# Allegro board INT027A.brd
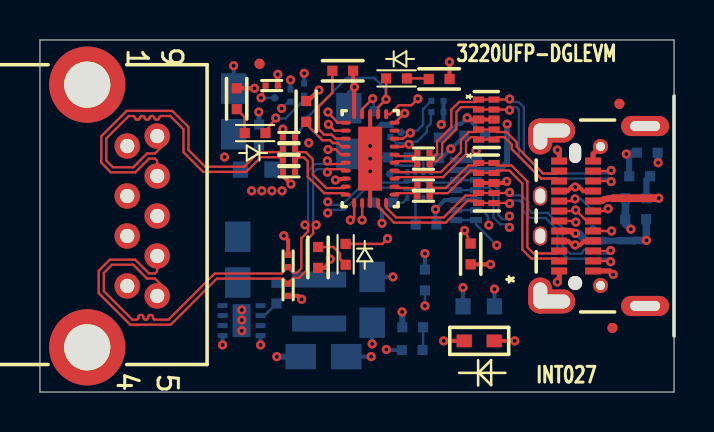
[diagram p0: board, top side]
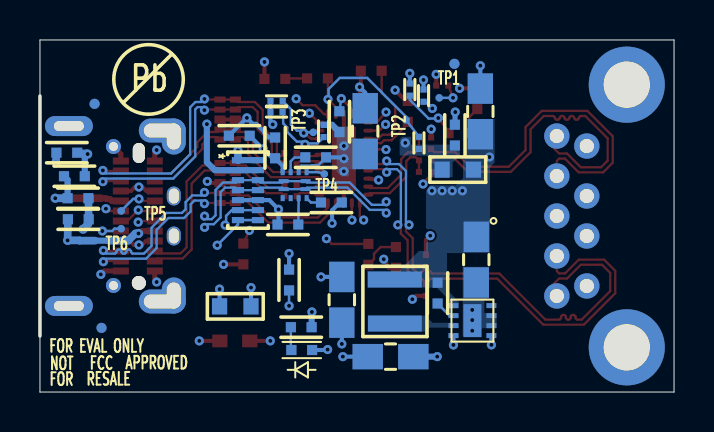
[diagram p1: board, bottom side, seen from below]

Outline 31.74 x 17.61 mm; copper layers: TOP, L2_GND, L3_PWR, L4_PWR, L5_GND, BOTTOM. Coordinates in mm from the lower left corner of the outline.
Outline path: 0,17.61 0,0 31.74,0 31.74,17.61 0,17.61

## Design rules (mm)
net group DIFFPAIR0: nets USB2_N0 USB2_P0
net group DIFFPAIR1: nets CTX1N CTX1P
net group DIFFPAIR2: nets CRX2N CRX2P
net group DIFFPAIR3: nets CTX2N CTX2P
net group DIFFPAIR4: nets CRX1N CRX1P
net group DIFFPAIR5: nets USB3_RX0N USB3_RX0P
net group DIFFPAIR6: nets USB3_TX0N USB3_TX0P
net group DIFFPAIR7: nets CTX2N_C CTX2P_C
net group DIFFPAIR8: nets CTX1N_C CTX1P_C
net group DP1: nets USB3_RX0N_C USB3_RX0P_C

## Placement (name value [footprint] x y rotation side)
C1  0.5uF  [0201]  12.47 12.16 0 top
C2  0.5uF  [0201]  19.2 11.96 0 top
C3  0.5uF  [0201]  12.46 11.59 0 top
C4  0.5uF  [0201]  19.2 11.4 0 top
C5  0.5uF  [0201]  19.2 10.36 0 top
C6  0.5uF  [0201]  19.2 9.8 0 top
C7  22uF  [0805]  9.7 14.04 90 bottom
C8  47uF  [0805]  15.46 13.05 270 bottom
C9  0.1uF  [0402]  10.97 12.85 90 bottom
C10  0.1uF  [0402]  21.77 12.82 0 bottom
C11  0.01uF  [0402]  19.97 12.21 90 bottom
C12  0.1uF  [0402]  17.94 11.74 180 bottom
C13  0.1uF  [0402]  19.33 8.38 0 bottom
C14  10uF  [0805]  9.9 6.62 270 bottom
C15  10uF  [0805]  16.63 4.62 90 bottom
C16  NC, 10uF  [0603]  21.97 4.28 0 bottom
C17  10uF  [0805]  14.19 1.77 0 bottom
D1  LED RED 0402  [LED_0402]  17.85 15.69 0 top
D2  LED YLW 0402  [LED_0402]  10.77 12.96 180 top
D3  LED Orange 0402  [LED_0402]  15.3 6.89 270 top
D4  ESD5Z6.0T1G  [SOD_523]  21.99 2.56 180 top
D5  LED Green  [LED_0402]  18.64 2.1 180 bottom
FB1  220 @ 100MHZ  [0603]  10.83 11.13 0 bottom
J1  USB3_TypeA_Connector  [USB3_TYPEA]  5.87 8.81 270 top
J2  TypeC_Receptacle_DualSMT_TOP  [USB_TYPEC_UT1211]  26.79 8.81 90 top
L1  1uH  [IND_NR3015]  13.98 4.53 90 bottom
NOREF  -  []  0 0 0 top
NOREF#2  -  []  -8.44 36.96 0 top
NOREF#3  -  []  46.18 36.96 0 top
NOREF#4  -  []  31.74 0 0 top
NOREF#5  -  []  -8.73 -17.08 0 top
NOREF#6  -  []  0 0 0 top
NOREF#7  -  [unnamed#2]  10.99 16.42 0 top
NOREF#8  -  [unnamed#2]  28.66 3.21 0 top
NOREF#9  -  [unnamed#2]  29.01 14.42 0 top
NOREF#10  -  []  0 17.61 0 top
NOREF#11  -  []  -67.49 -63.26 0 top
NOREF#12  -  []  69.68 -27.35 0 top
NOREF#13  -  [unnamed#2]  29.01 14.42 180 bottom
NOREF#14  -  [unnamed#2]  28.66 3.21 180 bottom
NOREF#15  -  [unnamed#2]  11 16.42 180 bottom
R1  NC, 10K  [0402]  15.16 16.07 0 top
R2  500R  [0402]  19.98 15.66 180 top
R3  200K  [0201]  11.6 15.33 180 top
R4  500R  [0402]  9.85 14.67 270 top
R5  4.7K  [0402]  13.33 14.04 90 top
R6  100K  [0201]  12.46 12.73 180 top
R7  100K  [0201]  12.47 11.02 180 top
R8  900K  [0402]  21.56 6.91 270 top
R9  500R  [0402]  13.92 6.73 90 top
R10  100K  [0201]  12.42 6.56 90 top
R11  100K  [0201]  12.42 5.12 270 top
R12  200K  [0201]  13.23 15.13 270 bottom
R13  200K  [0201]  12.54 14.83 270 bottom
R14  200K  [0201]  19.9 14.56 180 bottom
R15  NC, 10K  [0201]  19.9 14.01 180 bottom
R16  0  [0402]  16.75 13.53 90 bottom
R17  NC, 10K  [0201]  17.55 13.06 90 bottom
R18  200K  [0201]  12.77 12.46 90 bottom
R19  0  [0402]  30.4 11.97 180 bottom
R20  NC, 0  [0402]  30.02 10.79 180 bottom
R21  0  [0402]  29.84 9.7 180 bottom
R22  1.6K  [0402]  17.16 9.48 180 bottom
R23  NC, 0  [0402]  29.82 8.64 180 bottom
R24  0  [0402]  19.27 5.61 270 bottom
R25  178K  [0402]  11.84 4.95 90 bottom
R26  330  [0402]  18.66 3.24 180 bottom
TP1  15-mil TEST PAD  [15_MIL_ROUND_PROBE_POINT]  11.76 14.72 180 bottom
TP2  15-mil TEST PAD  [15_MIL_ROUND_PROBE_POINT]  13.42 13.61 90 bottom
TP3  15-mil TEST PAD  [15_MIL_ROUND_PROBE_POINT]  18.07 12.99 90 bottom
TP4  15-mil TEST PAD  [15_MIL_ROUND_PROBE_POINT]  17.51 10.91 0 bottom
TP5  15-mil TEST PAD  [15_MIL_ROUND_PROBE_POINT]  27.68 9.06 90 bottom
TP6  15-mil TEST PAD  [15_MIL_ROUND_PROBE_POINT]  27.68 8.17 90 bottom
U1  HD3SS3220  [RNH_QFN-30]  16.53 11.68 0 top
U2  TPD4E05U06  [DQA]  22.35 13.63 270 top
U3  TPD4E05U06  [DQA]  22.35 10.46 270 top
U4  TUSB211RWB  [RWB]  18.99 10.35 180 bottom
U5  TPD6E05U06  [RVZ]  21.33 10.1 270 bottom
U6  TPS62082DSGT  [DSG]  10.09 3.57 0 bottom

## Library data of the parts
C1-C9 C15 = CAP NP
C10-C13 = cc0402
C14 C16 C17 = CAP
D1-D3 D5 = DIODE_0
D4 = DIODE TAZ
FB1 = FERRITE BEAD
J1 = USB3_TYPEA_CONNECTOR
J2 = USBTypeC_Receptacle_TOPMount_0
L1 = INDUCTOR
R1 R5 R8 = RESISTOR
R2 R4 R9 R16 R19-R21 R23 R24 R26 = R
R3 R6 R7 R10-R15 R17 R18 = R_2
R22 = r0402
R25 = RES
TP1-TP6 = TEST POINT
U1 = HD3SS3220_0
U2 U3 = TPD4E05U06
U4 = TUSB211RWB
U5 = TPD6E05U06
U6 = TPS62082_0

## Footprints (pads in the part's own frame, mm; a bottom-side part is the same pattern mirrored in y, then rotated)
15_MIL_ROUND_PROBE_POINT
  round 0.381 smd: 1(0,0)
0201
  rect 0.305x0.305 smd: 1(-0.305,0) 2(0.305,0)
0402
  rect 0.508x0.508 smd: 1(-0.521,0) 2(0.521,0)
0603
  rect 0.762x0.813 smd: 1(-0.787,0) 2(0.787,0)
0805
  rect 1.524x1.27 smd: 1(-1.143,0) 2(1.143,0)
DQA
  rect 0.305x0.559 smd: 1(-1,-0.385) 2(-0.5,-0.385) 4(0.5,-0.385) 5(1,-0.385) 6(1,0.385) 7(0.5,0.385) 9(-0.5,0.385) 10(-1,0.385)
  rect 0.406x0.559 smd: 3(0,-0.385) 8(0,0.385)
DSG
  rect 0.5x0.25 smd: 1(-0.95,0.75) 2(-0.95,0.25) 3(-0.95,-0.25) 4(-0.95,-0.75) 5(0.95,-0.75) 6(0.95,-0.25) 7(0.95,0.25) 8(0.95,0.75)
  rect 0.9x1.65 smd: 9(0,0)
IND_NR3015
  rect 0.8x2.7 smd: 1(-1.1,0) 2(1.1,0)
LED_0402
  rect 0.508x0.508 smd: 1(-0.521,0) 2(0.521,0)
RNH_QFN-30
  oval 0.5x0.2 smd: 1(-1.225,1.8) 2(-1.225,1.4) 3(-1.225,1) 4(-1.225,0.6) 5(-1.225,0.2) 6(-1.225,-0.2) 7(-1.225,-0.6) 8(-1.225,-1) 9(-1.225,-1.4) 10(-1.225,-1.8) 16(1.225,-1.8) 17(1.225,-1.4) 18(1.225,-1) 19(1.225,-0.6) 20(1.225,-0.2) 21(1.225,0.2) 22(1.225,0.6) 23(1.225,1) 24(1.225,1.4) 25(1.225,1.8)
  oval 0.2x0.5 smd: 11(-0.8,-2.225) 12(-0.4,-2.225) 13(0,-2.225) 14(0.4,-2.225) 15(0.8,-2.225) 26(0.8,2.225) 27(0.4,2.225) 28(0,2.225) 29(-0.4,2.225) 30(-0.8,2.225)
  rect 1.2x3.2 smd: 31(0,0)
RVZ
  rect 0.305x0.61 smd: 1(-1.5,-0.5) 2(-1,-0.5) 3(-0.5,-0.5) 4(0,-0.5) 5(0.5,-0.5) 6(1,-0.5) 7(1.5,-0.5) 8(1.5,0.5) 9(1,0.5) 10(0.5,0.5) 11(0,0.5) 12(-0.5,0.5) 13(-1,0.5) 14(-1.5,0.5)
RWB
  rect 0.5x0.2 smd: 1(-0.55,0.2) 2(-0.55,-0.2) 7(0.55,-0.2) 8(0.55,0.2)
  rect 0.2x0.3 smd: 3(-0.6,-0.65) 4(-0.2,-0.65) 5(0.2,-0.65) 6(0.6,-0.65) 9(0.6,0.65) 10(0.2,0.65) 11(-0.2,0.65) 12(-0.6,0.65)
SOD_523
  rect 0.762x0.635 smd: 1(0.75,0) 2(-0.75,0)
unnamed#2
  round 0.508 smd: 1(0,0)
USB3_TYPEA
  round 1.27 hole 0.711: 1(-3.5,-1.5) 2(-1,-1.5) 3(1,-1.5) 4(3.5,-1.5) 5(4,0) 6(2,0) 7(0,0) 8(-2,0) 9(-4,0)
  round 3.81 hole 2.311: 10(-6.57,-3.5) 11(6.57,-3.5)
USB_TYPEC_UT1211
  round 0.7 hole 0.7 unplated: (-3.35,0)
  oval 1x0.6 hole 1x0.6 unplated: (3.15,0)
  round 0.75 hole 0.45: 1(-3.475,-1.27) 2(3.475,-1.27)
  oval 1x2.4 hole 0.5x1.5: 3(-4.5,-3.5) 4(4.5,-3.5)
  oval 0.95x0.7 hole 0.75x0.5: 5(-1,1.75) 6(1,1.75)
  oval 1.2x2.35 hole 0.7x1.85: 7(4.275,1.175) 8(-4.275,1.175)
  oval 1.8x1.2 hole 1.3x0.7: 9(-3.975,1.75) 10(3.975,1.75)
  rect 0.35x0.8 smd: A1(-2.75,0.8) A2(-2.25,0.8) A3(-1.75,0.8) A4(-1.25,0.8) A5(-0.75,0.8) A6(-0.25,0.8) A7(0.25,0.8) A8(0.75,0.8) A9(1.25,0.8) A10(1.75,0.8) A11(2.25,0.8) A12(2.75,0.8) B1(2.75,-0.9) B2(2.25,-0.9) B3(1.75,-0.9) B4(1.25,-0.9) B5(0.75,-0.9) B6(0.25,-0.9) B7(-0.25,-0.9) B8(-0.75,-0.9) B9(-1.25,-0.9) B10(-1.75,-0.9) B11(-2.25,-0.9) B12(-2.75,-0.9)

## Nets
5V_COM: C8.1 C15.1 C16.2(B) C17.2(B) D4.1(CATHODE) D5.2(A) J1.1(VBUS) J2.A4(VBUS1) J2.A9(VBUS2) J2.B4(VBUS3) J2.B9(VBUS4) R1.2 R2.1 R3.1 R4.1 R8.2 R9.1 R12.1 R13.1 R14.1 R15.1 U1.30(VDD5) U6.1(EN) U6.8(VIN)
GND: C7.2 C8.2 C9.2 C10.2 C11.2 C12.2 C13.2 C14.2(B) C15.2 C16.1(A) C17.1(A) D4.2(ANODE) J1.4(GND#4) J1.7(GND#7) J1.10(SHIELD0) J1.11(SHIELD1) J2.1(SHIELD1) J2.2(SHIELD2) J2.3(SHIELD3) J2.4(SHIELD4) J2.5(SHIELD5) J2.6(SHIELD6) J2.7(SHIELD7) J2.8(SHIELD8) J2.9(SHIELD9) J2.10(SHIELD10) J2.A1(GND0) J2.A12(GND1) J2.B1(GND2) J2.B12(GND3) R5.2 R6.2 R7.2 R10.2 R11.2 R16.1 R17.2 R22.2 R24.1 R26.2 U1.13(GND#13) U1.28(GND#28) U1.31(PPAD) U2.3(GND#3) U2.8(GND#8) U3.3(GND#3) U3.8(GND#8) U4.10(GND) U5.5(GND) U5.10(GND#10) U6.2(GND) U6.3(MODE) U6.9(PWPD)
VBUS_DET: R8.1 U1.5(VBUS_DET)
3P3V: C7.1 C10.1 C11.1 C14.1(A) FB1.1 L1.2 R25.2(B) U4.12(VCC) U6.5(VOS)
3P3V_VCC: C9.1 FB1.2 R18.1 U1.8(VCC33)
3220_ID: D1.1(K) R18.2 TP2.1 U1.27(ID)
ADDR: R15.2 R17.1 U1.22(ADDR)
C_CC1: J2.A5(CC1) R19.1 R23.1
C_CC2: J2.B5(CC2) R20.1 R21.1
CC1: R19.2 R20.2 U1.2(CC1) U5.1(NC1) U5.14(D1+)
CC2: R21.2 R23.2 U1.1(CC2) U5.2(NC2) U5.13(D1-)
CRX1N: J2.B10(SSRXN1) U1.15(RX1P) U3.4(D2+) U3.7(NC7)
CRX1P: J2.B11(SSRXP1) U1.14(RX1N) U3.5(D2-) U3.6(NC6)
CRX2N: J2.A10(SSRXN2) U1.18(RX2N) U2.5(D2-) U2.6(NC6)
CRX2P: J2.A11(SSRXP2) U1.19(RX2P) U2.4(D2+) U2.7(NC7)
CSBU1: J2.A8(SBU1) TP5.1 U5.7(NC6) U5.8(D3-)
CSBU2: J2.B8(SBU2) TP6.1 U5.6(NC5) U5.9(D3+)
CTX1N: C5.2 J2.A3(SSTXN1) U3.1(D1+) U3.10(NC10)
CTX1N_C: C5.1 U1.17(TX1P)
CTX1P: C6.2 J2.A2(SSTXP1) U3.2(D1-) U3.9(NC9)
CTX1P_C: C6.1 U1.16(TX1N)
CTX2N: C4.2 J2.B3(SSTXN2) U2.2(D1-) U2.9(NC9)
CTX2N_C: C4.1 U1.20(TX2N)
CTX2P: C2.2 J2.B2(SSTXP2) U2.1(D1+) U2.10(NC10)
CTX2P_C: C2.1 U1.21(TX2P)
CUR_MD: R1.1 U1.3(CURRENT_MODE)
DIR: R3.2 TP1.1 U1.11(DIR)
EN#_CC: R16.2 U1.29(ENN_CC)
EN#_MUX: R24.2 U1.12(ENN_MUX)
INT#_OUT3: R14.2 TP3.1 U1.23(INT_N_OUT3)
PORT: R5.1 U1.4(PORT)
SCL_OUT2: D2.1(K) R12.2 U1.26(SCL_OUT2)
SDA_OUT1: D3.1(K) R13.2 U1.25(SDA_OUT1)
U8_PG: R25.1(A) U6.6(PG)
U8_SW: L1.1 U6.7(SW)
USB2_N0: J1.2(DM) J2.A7(DN1) J2.B7(DN2) U4.1(D1M) U4.8(D2M) U5.3(NC3) U5.12(D2+)
USB2_P0: J1.3(DP) J2.A6(DP1) J2.B6(DP2) U4.2(D1P) U4.7(D2P) U5.4(NC4) U5.11(D2-)
USB3_RX0N: C1.1 J1.8(SSTXN)
USB3_RX0N_C: C1.2 R6.1 U1.9(RXP)
USB3_RX0P: C3.1 J1.9(SSTXP)
USB3_RX0P_C: C3.2 R7.1 U1.10(RXN)
USB3_TX0N: J1.5(SSRXN) R10.1 U1.6(TXP)
USB3_TX0P: J1.6(SSRXP) R11.1 U1.7(TXN)
VCONN_FAULT#: U1.24(VCONN_FAULT_N)
N16911818: C12.1 U4.11(VREG)
N16911898: C13.1 U4.5(RSTN)
N16911900: R22.1 U4.6(EQ)
N16922242: TP4.1 U4.9(ENA_HS)
N16960198: D5.1(K) R26.1
N16963575: D3.2(A) R9.2
N16963631: D2.2(A) R4.2
N16967109: D1.2(A) R2.2

Pads without a net: NOREF#7 1; NOREF#8 1; NOREF#9 1; NOREF#13 1; NOREF#14 1; NOREF#15 1; U4 3 4; U6 4

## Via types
v1: diameter 0.457, hole 0.203, TOP to BOTTOM, 100 vias

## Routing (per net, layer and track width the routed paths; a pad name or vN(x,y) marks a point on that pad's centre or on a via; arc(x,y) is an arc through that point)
5V_COM: length 22.7
  TOP w0.203: D4.1 v1(20.21,2.56) ; R1.2 15.68,15.32 v1(15.74,15.26) 15.73,15.25 U1.30 ; R9.1 14.28,6.21 v1(14.53,6.64) ; J2.B4 27.19,10.06 27,10.25 v1(26.79,10.25) 26.61,10.25 26.42,10.06 J2.A9 ; J2.A4 26.44,7.56 26.64,7.36 v1(26.79,7.36) 27.05,7.36 27.24,7.56 J2.B9 ; R8.2 v1(22.56,6.39) ; R3.1 v1(11.91,15.89) ; R4.1 v1(10.74,15.19) ; R2.1 v1(20.51,16.52)
  L4_PWR w0.203: 3.55,12.31 J1.1 ; J1.1 5.18,12.31 ; J1.1 4.37,13.12 ; J1.1 4.37,11.49
  BOTTOM w0.203: C15.1 v1(16.63,2.41) ; U6.8 v1(11.04,2.35) ; R12.1 v1(13.23,15.94) ; C8.1 15.46,14.98 v1(15.74,15.26) ; C17.2 v1(16.58,1.77) ; v1(20.09,13.39) 20.21,13.5 R15.1 20.2,14.01 R14.1 ; 18.14,2.1 D5.2 17.37,2.1 v1(17.34,2.13) ; C16.2 v1(22.75,5.15) ; U6.1 v1(9.14,2.36) ; R13.1 v1(12.54,15.61)
GND: length 117.5
  TOP w0.203: R11.2 12.93,4.81 v1(13.1,4.64) ; v1(23.37,10.54) 23.17,10.46 U3.8 U3.3 ; U1.28 v1(16.53,12.31) v1(16.53,11.68) v1(16.53,11.04) U1.13 ; R5.2 13.42,14.56 v1(13.96,15.11) ; D4.2 v1(23.77,2.56) ; U2.8 U2.3 21.47,13.63 v1(21.39,13.72) ; R6.2 v1(12.16,13.15) ; v1(12.21,7.82) 12.42,7.6 R10.2 ; R7.2 12.16,10.81 v1(12.57,10.41)
  TOP w0.254: v1(25.9,5.5) 25.99,5.6 J2.A1 ; J2.B12 28.53,6.06 v1(28.7,5.89) ; J2.A12 25.99,12.02 v1(25.9,12.11) ; J2.2 27.69,11.91 J2.B1
  L2_GND w0.203: 4.45,15.38 J1.10 2.37,13.29 ; J2.2 28.62,12.28 ; J2.2 28.06,12.83 ; J2.2 27.51,12.28 ; J2.2 28.06,11.73 ; J2.7 25.62,13.86 ; J2.7 24.27,13.08 ; J2.7 26.97,13.08 ; J2.5 25.57,7.81 ; J2.5 25.04,7.15 ; J2.5 24.52,7.81 ; J2.5 25.04,8.46 ; J1.4 4.37,6.12 ; J1.4 3.55,5.31 ; J1.4 5.18,5.31 ; J1.4 4.37,4.49 ; J2.3 30.3,4.98 ; J2.3 30.3,3.63 ; J2.3 28.92,4.31 ; 28.06,4.78 J2.1 ; J2.1 28.06,5.88 ; J2.1 27.51,5.33 ; J2.1 28.62,5.33 ; 24.27,4.83 J2.9 ; J2.9 25.04,5.91 ; J2.9 25.04,3.75 ; J2.6 25.04,10.46 ; J2.6 24.52,9.81 ; J2.6 25.04,9.15 ; J2.6 25.57,9.81 ; 2.37,4.32 J1.11 4.45,2.24 ; 5.05,8.81 J1.7 ; J1.7 5.87,7.99 ; J1.7 5.87,9.62 ; J1.7 6.68,8.81 ; J2.10 25.04,13.86 ; J2.10 25.04,11.7 ; J2.10 24.27,12.78 ; 30.3,12.63 J2.4 ; J2.4 30.3,13.98 ; J2.4 28.92,13.31 ; J2.8 26.97,4.53 ; J2.8 24.27,4.53 ; J2.8 25.62,3.75
  L5_GND w0.203: J2.10 25.04,13.86 ; J2.10 25.04,11.7 ; J2.10 24.27,12.78 ; 27.51,12.28 J2.2 ; J2.2 28.06,11.73 ; J2.2 28.62,12.28 ; J2.2 28.06,12.83 ; J2.5 25.57,7.81 ; J2.5 25.04,8.46 ; J2.5 24.52,7.81 ; J2.5 25.04,7.15 ; J2.1 28.06,5.88 ; J2.1 28.62,5.33 ; J2.1 28.06,4.78 ; J2.1 27.51,5.33 ; 24.27,13.08 J2.7 ; J2.7 25.62,13.86 ; J2.7 26.97,13.08 ; J1.4 4.37,6.12 ; J1.4 4.37,4.49 ; J1.4 5.18,5.31 ; J1.4 3.55,5.31 ; 4.45,2.24 J1.11 2.37,4.32 ; J2.3 30.3,4.98 ; J2.3 28.92,4.31 ; J2.3 30.3,3.63 ; 2.37,13.29 J1.10 4.45,15.38 ; 24.27,4.83 J2.9 ; J2.9 25.04,5.91 ; J2.9 25.04,3.75 ; J1.7 5.87,9.62 ; J1.7 5.87,7.99 ; J1.7 6.68,8.81 ; J1.7 5.05,8.81 ; 25.04,9.15 J2.6 ; J2.6 24.52,9.81 ; J2.6 25.57,9.81 ; J2.6 25.04,10.46 ; 25.62,3.75 J2.8 ; J2.8 24.27,4.53 ; J2.8 26.97,4.53 ; 28.92,13.31 J2.4 ; J2.4 30.3,13.98 ; J2.4 30.3,12.63
  BOTTOM w0.127: U4.10 18.79,11.19 18.66,11.32 18.14,11.32 18.12,11.34 17.82,11.34 C12.2
  BOTTOM w0.203: v1(17.12,8.44) 17.12,8.45 17.12,9.09 16.73,9.48 R22.2 ; R24.1 v1(19.27,6.93) ; C10.2 22.28,12.82 v1(21.39,13.72) 21.09,13.42 20.92,13.42 20.51,13 20.51,12.96 20.28,12.74 C11.2 ; C7.2 v1(9.7,16.32) ; 16.59,11.62 v1(16.53,11.68) 16.59,11.74 C12.2 ; C15.2 v1(17.67,5.76) ; C16.1 v1(21.18,5.22) ; C13.2 19.8,8.44 19.8,9.14 v1(19.8,9.14) 20.26,9.6 U5.10 U5.5
  BOTTOM w0.254: C9.2 v1(10.96,14.01)
  BOTTOM w0.305: C17.1 v1(11.86,1.77) ; v1(18.13,4.01) 18.14,3.99 R26.2 ; R16.1 17.11,13.37 R17.2
  vias: v1(10.1,4.11) v1(10.1,3.6) v1(10.1,3.07)
VBUS_DET: length 10.6
  TOP w0.122: U1.5 15.07,11.88 14.81,12.14 v1(14.42,12.13) ; R8.1 v1(21.26,8.08)
  L3_PWR w0.122: v1(14.42,12.13) 16.36,10.2 19.82,10.2 21.26,8.76 v1(21.26,8.08)
3P3V: length 2.6
  BOTTOM w0.203: U4.12 19.59,11.32 C11.1 20.1,11.69 v1(20.57,12.16) 20.59,12.16 C10.1
  vias: v1(9.24,11.76) v1(10.6,10.07) v1(11.1,10.07) v1(11.61,10.07) v1(12.12,10.07)
3P3V_VCC: length 3.4
  TOP w0.203: U1.8 v1(14.79,10.61)
  L3_PWR w0.203: v1(14.79,10.61) 14.6,10.61 14.5,10.51 14.21,10.51 13.53,11.19 13.53,12.39 v1(13.46,12.46)
3220_ID: length 8.6
  TOP w0.122: U1.27 16.93,14.25 v1(17.33,14.64) 17.33,14.65 D1.1
  BOTTOM w0.122: v1(17.33,14.64) 17.29,14.68 17.29,15.16 16.73,15.71 15.36,15.71 14.77,15.12 14.76,15.12 14.66,15.03 14.66,15.02 13.42,13.77 TP2.1 13.42,13.61 R18.2
ADDR: length 4.1
  TOP w0.122: U1.22 18.15,12.28 v1(18.47,12.39)
  BOTTOM w0.122: R15.2 19.57,13.98 19.57,13.44 19.37,13.24 19.37,13.01 18.88,12.53 18.57,12.53 v1(18.47,12.39) 18.43,12.44 17.86,12.44 17.55,12.75 R17.1
C_CC1: length 10.3
  TOP w0.305: v1(26.81,7.93) 26.73,8.02 26.63,8.02 26.59,8.06 J2.A5
  L3_PWR w0.381: v1(30.36,7.59) 30.36,10.89 v1(30.95,11.47)
  BOTTOM w0.305: 28.3,7.57 28.99,7.57
  BOTTOM w0.381: v1(26.81,7.93) 26.97,7.93 27.33,7.57 28.3,7.57 ; R23.1 v1(30.36,7.59) 29.76,7.59 29.75,7.57 28.99,7.57 ; R19.1 v1(30.95,11.47)
C_CC2: length 5.1
  TOP w0.305: J2.B5 28.15,9.56 28.24,9.65 28.4,9.65 28.44,9.7 28.68,9.7
  TOP w0.381: 28.68,9.7 v1(30.98,9.7)
  BOTTOM w0.305: R20.1 30.36,10.61 R21.1
  BOTTOM w0.381: v1(30.98,9.7) R21.1
CC1: length 23.2
  TOP w0.122: v1(14.44,13.39) 14.75,13.08 U1.2
  L4_PWR w0.305: v1(29.36,11.9) 29.16,11.71 28.49,11.71 28.34,11.55 28.14,11.55 27.64,11.05 25.95,11.05 25.62,11.39 22.89,11.39 22.19,12.09 v1(21.83,12.09) 20.95,12.97 20.95,13.38 20.42,13.91 19.55,13.91 19.13,13.49 19.13,12.21 18.74,11.82 18.23,11.82 16.66,13.39 v1(14.44,13.39)
  BOTTOM w0.305: R20.2 29.5,11.76 v1(29.36,11.9) 29.43,11.97 R19.2 ; U5.14 U5.1
  BOTTOM w0.381: U5.1 21.83,11.6 v1(21.83,12.09)
CC2: length 30
  TOP w0.122: U1.1 14.89,13.48 v1(14.42,14.01)
  L4_PWR w0.254: v1(14.42,14.01) 17.51,14.01 18.03,14.52 18.03,14.85 18.49,15.31 21,15.31 22.88,13.43 23.36,13.43 v1(23.39,13.4) 23.74,13.4 24.61,14.27 27.12,14.27 28.93,12.46 29.76,12.46 30.02,12.21 30.02,9.85 29.59,9.42 v1(29.59,8.15)
  BOTTOM w0.305: U5.13 U5.2 22.99,11.1 23.39,11.5 v1(23.39,13.4)
  BOTTOM w0.381: R21.2 R23.2 29.32,8.41 v1(29.59,8.15)
CRX1N: length 15.6
  TOP w0.114: v1(28.57,7.08) 28.57,7.06 J2.B10 ; U1.15 17.33,9.23 17.83,8.73 20.21,8.73 21.31,9.83 21.85,9.83 21.96,9.95 U3.4 U3.7 23.48,9.96 v1(23.51,9.99)
  BOTTOM w0.114: v1(23.51,9.99) 23.66,9.83 24.12,9.83 24.46,9.5 24.46,9.14 24.64,8.96 25.42,8.96 26.16,8.22 26.16,7.31 26.54,6.93 27.12,6.93 27.19,7 27.19,7.06 27.26,7.13 27.36,7.13 27.43,7.06 27.43,7 27.5,6.93 27.6,6.93 27.67,7 27.67,7.06 27.74,7.13 27.84,7.13 27.91,7.06 27.91,7 27.98,6.93 28.42,6.93 v1(28.57,7.08)
CRX1P: length 15.6
  TOP w0.114: v1(28.57,6.52) 28.53,6.56 J2.B11 ; U1.14 16.93,9.27 17.72,8.48 20.31,8.48 21.42,9.58 21.84,9.58 U3.5 U3.6 23.48,9.46 v1(23.51,9.43)
  BOTTOM w0.114: v1(23.51,9.43) 23.66,9.58 24.01,9.58 24.2,9.39 24.2,9.03 24.53,8.7 25.31,8.7 25.9,8.12 25.9,7.2 26.43,6.67 28.42,6.67 v1(28.57,6.52)
CRX2N: length 10.6
  TOP w0.114: J2.A10 25.87,10.68 25.1,10.68 23.62,12.16 23.62,12.38 23.25,12.76 22.85,12.76 U2.6 U2.5 21.84,12.76 21.58,12.76 21.33,12.51 21.33,11.9 20.18,10.75 17.83,10.75 U1.18
CRX2P: length 10.6
  TOP w0.114: U1.19 17.83,11 20.07,11 21.08,12.01 21.08,12.62 21.47,13.01 21.84,13.01 U2.4 U2.7 22.73,13.12 22.85,13.01 23.35,13.01 23.87,12.49 23.87,12.26 25.2,10.93 25.87,10.93 J2.A11
CSBU1: length 15.9
  TOP w0.122: J2.A8 26.68,9.56 v1(26.79,9.66)
  L3_PWR w0.122: v1(26.79,9.66) 28.73,9.66 29.08,9.31 29.08,7.79 28.83,7.54 28.41,7.54 27.13,6.26 23.96,6.26 v1(22.87,7.34)
  BOTTOM w0.122: U5.8 U5.7 21.83,8.38 v1(22.87,7.34) ; v1(26.79,9.66) 27.08,9.66 TP5.1
CSBU2: length 11.5
  TOP w0.122: J2.B8 v1(28.62,8.06)
  L3_PWR w0.122: v1(22.47,8.35) 24.18,6.65 27.02,6.65 28.43,8.06 v1(28.62,8.06)
  BOTTOM w0.122: v1(28.62,8.06) 28.13,8.06 28.01,8.17 TP6.1 ; U5.9 U5.6 22.14,9.1 22.43,8.81 22.43,8.4 v1(22.47,8.35)
CTX1N: length 10.9
  TOP w0.114: J2.A3 25.87,6.93 24.71,6.93 24.4,7.24 24.4,10.54 23.61,11.33 22.85,11.33 U3.10 U3.1 21.84,11.33 21.45,11.33 20.31,10.2 19.65,10.2 C5.2
CTX1N_C: length 1.2
  TOP w0.114: U1.17 17.83,10.2 18.74,10.2 C5.1
CTX1P: length 10.9
  TOP w0.114: C6.2 19.65,9.95 20.42,9.95 21.55,11.08 21.84,11.08 U3.2 U3.9 22.85,11.08 23.5,11.08 24.15,10.43 24.15,7.13 24.6,6.68 25.87,6.68 J2.A2
CTX1P_C: length 1.2
  TOP w0.114: U1.16 17.83,9.95 18.74,9.95 C6.1
CTX2N: length 15.1
  TOP w0.114: J2.B3 28.57,10.56 v1(28.59,10.53) ; v1(23.51,14.1) 23.48,14.13 23.08,14.13 U2.9 U2.2 21.84,14.26 21.09,14.26 20.85,14.01 20.85,13.15 20.14,12.44 20.14,11.81 19.87,11.55 19.65,11.55 C4.2
  BOTTOM w0.114: v1(28.59,10.53) 28.44,10.68 25.07,10.68 23.97,11.78 23.97,14.14 23.85,14.26 23.66,14.26 v1(23.51,14.1)
CTX2N_C: length 1.2
  TOP w0.114: U1.20 17.83,11.55 18.74,11.55 C4.1
CTX2P: length 15.1
  TOP w0.114: v1(23.51,14.66) 23.48,14.63 U2.10 U2.1 21.84,14.51 20.98,14.51 20.59,14.12 20.59,13.25 19.88,12.54 19.88,11.92 19.77,11.8 19.65,11.8 C2.2 ; J2.B2 28.57,11.06 v1(28.59,11.09)
  BOTTOM w0.114: v1(23.51,14.66) 23.66,14.51 23.96,14.51 24.23,14.24 24.23,11.88 25.18,10.93 28.44,10.93 v1(28.59,11.09)
CTX2P_C: length 1.2
  TOP w0.114: C2.1 18.74,11.8 17.83,11.8 U1.21
CUR_MD: length 4.7
  TOP w0.122: U1.3 14.8,12.68 14.6,12.87 14.23,12.87 13.96,13.15 13.96,14.29 14.64,14.97 R1.1
DIR: length 11.4
  TOP w0.122: v1(11.07,14.72) 11.06,14.71 R3.2 ; v1(15.54,8.6) 15.73,8.79 U1.11
  L3_PWR w0.122: v1(11.07,14.72) 10.43,14.09 10.43,13.35 13.86,9.92 14.96,9.92 15.29,9.59 15.29,8.86 v1(15.54,8.6)
  BOTTOM w0.122: v1(11.07,14.72) 11.07,14.72 TP1.1
EN#_CC: length 1.6
  TOP w0.122: v1(16.66,14.68) 16.13,14.15 U1.29
  BOTTOM w0.122: R16.2 v1(16.66,14.68)
EN#_MUX: length 8.2
  TOP w0.122: U1.12 16.13,8.61 v1(16.12,8.6)
  L3_PWR w0.122: v1(16.12,8.6) 16.12,7.94 15.74,7.56 15.74,6.77 17.5,5.02 18.56,5.02 v1(19.27,4.31)
  BOTTOM w0.122: R24.2 v1(19.27,4.31)
INT#_OUT3: length 3.5
  TOP w0.122: v1(18.54,12.96) 18.17,12.68 U1.23
  BOTTOM w0.122: R14.2 19.18,14.15 19.18,13.37 18.88,13.08 18.66,13.08 v1(18.54,12.96) 18.51,12.99 TP3.1
PORT: length 2.6
  TOP w0.122: U1.4 15.11,12.28 14.92,12.45 14.66,12.45 14.52,12.6 14.14,12.6 13.33,13.41 R5.1
SCL_OUT2: length 13.5
  TOP w0.122: D2.1 11.29,13.03 v1(11.81,13.71) ; v1(18.92,14.67) 18.59,14.35 17.96,14.35 17.52,13.9 U1.26
  L3_PWR w0.122: v1(11.81,13.71) 11.78,13.7 11.78,13.95 11.68,14.05 11.68,14.39 11.98,14.7 14.73,14.7 15.36,14.06 17.52,14.06 18.16,14.7 18.9,14.7 v1(18.92,14.67)
  BOTTOM w0.122: R12.2 13.23,14.62 12.29,13.68 11.83,13.68 v1(11.81,13.71)
SDA_OUT1: length 24.1
  TOP w0.122: U1.25 17.78,13.48 v1(18.25,13.95) ; v1(17.4,7.67) 17.14,7.41 D3.1
  L3_PWR w0.122: v1(12.1,14.19) 12.5,14.19 13.8,12.88 17.19,12.88 v1(18.25,13.95) 18.32,14.01 18.79,14.01 19.93,12.87 19.93,11.98 22.02,9.89 22.02,7.67 21.23,6.88 20.04,6.88 19.24,7.67 v1(17.4,7.67)
  BOTTOM w0.122: v1(12.1,14.19) 12.44,14.52 12.54,14.52
U8_PG: length 1
  BOTTOM w0.122: R25.1 11.24,3.83 U6.6
USB2_N0: length 29.1
  TOP w0.114: J2.B7 27.37,8.56 v1(26.82,9.1) 26.78,9.06 J2.A7
  L3_PWR w0.114: J1.2 6.31,9.81 7.15,8.96 7.39,8.96 7.47,9.03 7.47,9.09 7.54,9.16 7.64,9.16 7.71,9.09 7.71,9.03 7.78,8.96 7.88,8.96 7.95,9.03 7.95,9.09 8.02,9.16 8.12,9.16 8.19,9.09 8.19,9.03 8.26,8.96 9.67,8.96 10.08,9.37 10.29,9.37 10.29,9.36 14.26,9.36 v1(14.41,9.52) ; v1(23.5,8.8) 23.66,8.65 24.24,8.65 24.51,8.92 25.54,8.92 25.61,8.99 25.61,9.22 25.68,9.29 25.78,9.29 25.85,9.22 25.85,8.99 25.92,8.92 26.02,8.92 26.09,8.99 26.09,9.22 26.16,9.29 26.26,9.29 26.33,9.22 26.33,8.99 26.4,8.92 26.64,8.92 v1(26.82,9.1)
  BOTTOM w0.114: v1(23.5,8.8) 23.35,8.65 23.15,8.65 22.95,8.84 22.95,10.11 22.58,10.48 21.95,10.48 U5.3 U5.12 20.71,10.48 19.62,10.48 U4.1 U4.8 18.37,10.48 16.24,10.48 15.13,9.36 14.56,9.36 v1(14.41,9.52)
USB2_P0: length 29.1
  TOP w0.114: J2.B6 28.33,9.06 v1(28.44,9.17) ; J2.A6 26.77,8.56 v1(26.83,8.5)
  L3_PWR w0.114: J1.3 6.21,7.81 7.11,8.7 9.77,8.7 10.18,9.11 14.26,9.11 v1(14.41,8.96) ; v1(28.44,9.17) 28.29,9.17 27.62,8.5 v1(26.83,8.5) 26.66,8.67 24.62,8.67 24.34,8.39 23.66,8.39 v1(23.5,8.24)
  BOTTOM w0.114: v1(14.41,8.96) 14.56,9.11 15.23,9.11 16.35,10.22 18.37,10.22 U4.7 U4.2 19.62,10.22 20.71,10.22 U5.11 U5.4 21.95,10.22 22.48,10.22 22.7,10 22.7,8.74 23.04,8.39 23.35,8.39 v1(23.5,8.24)
USB3_RX0N: length 17.2
  TOP w0.114: C1.1 12,12 11.48,12 10.96,12 10.22,11.27 8.27,11.27 7.44,12.1 7.44,13.25 6.62,14.06 4.34,14.06 3.07,12.79 3.07,11.47 3.55,10.99 4.77,10.99 5.46,11.68 5.75,11.68 5.87,11.56 J1.8
USB3_RX0N_C: length 4.4
  TOP w0.114: U1.9 15.23,10.2 14.33,10.2 13.66,10.88 13.66,11.65 13.31,12 12.93,12 C1.2 12.77,12.73 R6.1
USB3_RX0P: length 17.2
  TOP w0.114: C3.1 12,11.75 11.48,11.75 11.06,11.75 10.33,11.02 8.17,11.02 7.18,12 7.18,13.15 6.52,13.81 6.04,13.81 5.97,13.74 5.97,13.7 5.89,13.63 5.79,13.63 5.72,13.7 5.72,13.74 5.65,13.81 5.55,13.81 5.48,13.74 5.48,13.7 5.41,13.63 5.31,13.63 5.24,13.7 5.24,13.74 5.17,13.81 5.07,13.81 5,13.74 5,13.7 4.93,13.63 4.83,13.63 4.76,13.7 4.76,13.74 4.69,13.81 4.44,13.81 3.32,12.69 3.32,11.58 3.66,11.24 4.67,11.24 5.36,11.93 5.75,11.93 6.09,12.27 6.09,12.58 J1.9
USB3_RX0P_C: length 4.4
  TOP w0.114: R7.1 12.77,11.02 C3.2 12.93,11.75 13.21,11.75 13.41,11.55 13.41,10.77 14.23,9.95 15.23,9.95 U1.10
USB3_TX0N: length 24.8
  TOP w0.114: J1.5 6.17,5.1 6.17,5.27 5.75,5.68 5.35,5.68 4.66,6.37 3.61,6.37 3.2,5.96 3.2,5.05 4.62,3.62 4.86,3.62 4.93,3.7 4.93,3.78 5,3.85 5.1,3.85 5.17,3.78 5.17,3.7 5.25,3.62 5.35,3.62 5.42,3.7 5.42,3.78 5.49,3.85 5.59,3.85 5.66,3.78 5.66,3.7 5.73,3.62 6.44,3.62 8.75,5.93 12.1,5.93 R10.1 12.42,6.21 12.67,5.96 12.87,5.96 13.08,6.18 13.08,7.7 13.42,8.03 13.42,8.29 v1(13.27,8.36) ; U1.6 15.23,11.4 14.54,11.4 v1(14.39,11.56)
  BOTTOM w0.114: v1(14.39,11.56) 14.23,11.4 13.77,11.4 13.42,11.06 13.42,8.51 v1(13.27,8.36)
USB3_TX0P: length 24.8
  TOP w0.114: J1.6 5.87,6.05 5.75,5.93 5.46,5.93 4.77,6.62 3.5,6.62 2.94,6.06 2.94,4.95 4.52,3.37 6.55,3.37 8.85,5.67 12.17,5.67 R11.1 12.42,5.46 12.67,5.71 12.97,5.71 13.34,6.08 13.34,7.59 13.68,7.93 13.68,8.29 v1(13.83,8.36) ; v1(14.39,11) 14.54,11.15 15.23,11.15 U1.7
  BOTTOM w0.114: v1(14.39,11) 14.23,11.15 13.87,11.15 13.68,10.95 13.68,8.51 v1(13.83,8.36)
N16911818: length 1.4
  BOTTOM w0.122: U4.11 19.19,11.54 19,11.73 18.47,11.73 C12.1
N16911898: length 1.3
  BOTTOM w0.122: C13.1 18.79,9.59 U4.5
N16911900: length 0.8
  BOTTOM w0.122: R22.1 18.18,9.48 U4.6
N16922242: length 0.9
  BOTTOM w0.122: TP4.1 17.82,11 U4.9
N16960198: length 1.2
  BOTTOM w0.122: D5.1 19.18,2.13 R26.1
N16963575: length 1.9
  TOP w0.122: R9.2 14.69,7.25 15.02,6.92 15.02,6.65 D3.2
N16963631: length 1.4
  TOP w0.122: R4.2 10.25,13.75 D2.2
N16967109: length 1.1
  TOP w0.122: D1.2 19.44,15.69 R2.2

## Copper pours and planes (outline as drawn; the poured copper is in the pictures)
5V_COM on L4_PWR: 7.74,1.03 3.27,5.51 3.27,16.73 21.08,16.73 21.08,16.05 17.06,16.05 16,14.98 14.68,14.98 14.68,14.44 14.66,14.42 13.87,14.42 13.41,13.96 13.41,11.96 14.26,11.1 18.89,11.1 19.51,11.72 19.51,13.2 19.91,13.6 20.32,13.6 20.32,12.91 20.06,12.65 20.06,11.14 18.77,9.85 13.85,9.85 11.2,12.5 8.2,12.5 7.95,12.26 7.95,11.26 9.85,9.37 9.85,7.58 10.78,6.64 14.04,6.64 14.35,6.95 15,6.95 18.37,3.59 21.97,3.59 21.97,10.58 27.33,10.58 27.33,1.03
GND on BOTTOM: 9.27,6.27 9.27,4.77 9.49,4.54 9.49,3.95 8.94,3.95 8.91,3.98 8.88,3.95 8.88,3.19 9.6,3.19 9.62,3.17 9.62,2.76 10.54,2.76 10.59,2.81 10.59,6.27
GND on BOTTOM: 16.27,10.78 16.27,11.15 14.93,11.15 14.93,12.68 16.27,12.68 16.27,13.28 16.89,13.27 17,13.27 17,12.74 16.89,12.74 16.89,11.02 16.65,10.78
GND on L2_GND, L5_GND: 0.38,0.42 31.36,0.42 31.36,17.19 0.38,17.19 ; 2 cut-outs
3P3V on BOTTOM: 10.82,4.18 10.79,4.21 10.79,4.54 11.37,5.12 11.37,6.95 9.22,6.95 9.22,11.25 8.99,11.48 8.99,13.66 10.4,13.66 10.4,11.76 10.56,11.61 10.56,10.71 10.94,10.33 12.42,10.33 12.42,7.05 12.77,7.05 13.76,6.06 15.36,6.06 15.36,5.22 11.88,5.22 11.3,4.64 11.3,4.18
3P3V on L4_PWR: 8.6,11.77 8.6,11.32 12.51,7.41 15.18,7.41 16.1,6.49 19.98,6.49 21.21,7.72 21.21,12.14 20.92,12.42 20.38,12.42 20.17,12.21 20.18,12.19 20.18,10.71 18.84,9.37 13.69,9.37 10.91,12.14 8.97,12.14
3P3V_VCC on BOTTOM: 10.72,12.36 10.72,11.85 11.09,11.47 11.09,10.75 12.13,10.75 12.2,10.81 12.2,11.63 12.41,11.83 13.71,11.83 13.74,11.86 13.74,12.64 13.61,12.77 13.18,12.77 13.18,12.38 10.74,12.38 10.72,12.36
U8_SW on BOTTOM: 10.85,3.46 12.08,3.46 12.44,3.82 15.15,3.82 15.15,3.03 15.14,3.01 12.45,3.01 12.25,3.21 10.85,3.21 10.85,3.45

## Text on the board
BOTTOM: LAYER 6 - BOTTOM | 6
Ref Des/Assembly Bottom: ASSEMBLY BOTTOM
Board Geometry/Soldermask Bottom: SOLDERMASK BOTTOM
Package Geometry/Pastemask Bottom: PASTEMASK BOTTOM | 12
Ref Des/Silkscreen Bottom: APPROVED | FCC | RESALE | NOT | FOR | FOR EVAL ONLY | Pb | SILKSCREEN BOTTOM
TOP: LAYER 1 - TOP | 1
Ref Des/Assembly Top: ASSMBLY TOP
Board Geometry/Soldermask Top: SOLDERMASK TOP
Package Geometry/Pastemask Top: PASTEMASK TOP | 11
Ref Des/Silkscreen Top: 3220UFP-DGLEVM | INT027 | SILKSCREEN TOP
L2_GND: LAYER 2 - GND | 2
L3_PWR: LAYER 3 - SIGNAL | 3
L4_PWR: LAYER 4 - PWR | 4
L5_GND: LAYER 5 - GND | 5
XSECTION_CHART: *  SURFACE - AIR 0 MIL | *  DIELECTRIC - SOLDERMASK_LPI_0.8M 0.8 MIL | L1: TOP CONDUCTOR - COPPER_1/2OZ_PLATED 1.4 MIL | *  DIELECTRIC - FILL_0.080 3.15 MIL | L2: L2_GND PLANE - COPPER_1.0OZ 1.4 MIL | *  DIELECTRIC - FILL_0.100 3.94 MIL | L3: L3_PWR PLANE - COPPER_1.0OZ 1.4 MIL | *  DIELECTRIC - CORE_1.00 39.37 MIL | L4: L4_PWR PLANE - COPPER_1.0OZ 1.4 MIL | L5: L5_GND PLANE - COPPER_1.0OZ 1.4 MIL | L6: BOTTOM CONDUCTOR - COPPER_1/2OZ_PLATED 1.4 MIL | DESIGN CROSS SECTION CHART | ___________________________ | TOTAL THICKNESS 63.55 MIL | 1-6
DIMENSION: ALL 4.5 MIL LINES WITH 5.5 MIL SPACED ON LAYERS 1,3 AND 6 | SHALL BE 50 OHM SINGLE ENDED IMPEDANCE +/-10% | SHALL BE 90 OHM DIFFERENTIAL IMPEDANCE +/-10% | LY1-SIGNAL | LY2-GND PLANE | LY3-SIGNAL | LY4-PWR PLANE | LY5-GND PLANE | LY6-SIGNAL | STACK-UP | ALL 4.8 MIL LINES ON ALL LAYERS | CONTROLLED IMPEDANCE DESIGN | MINIMUM COPPER WEIGHT | 1/2 oz | 1 oz | FABRICATION DRAWING
PAGE_OUTLINE: LAYER 13 - FAB
User.7: A1
User.10: FIGURE | SIZE | 91.0 | 28.0 | 17.72 | 8.0 | 27.56 | 72.83x27.56 | 59.06x19.69 | 51.18x27.56 | 29.53x19.69 | 39.37x23.62 | DRILL CHART: TOP to BOTTOM | ALL UNITS ARE IN MILS | TOLERANCE | +3.0/-3.0 | +3.15/-3.15 | +3.0/-8.0 | +3.0/-3.94 | PLATED | NON-PLATED | QTY | 2 | 9 | 100 | 1
